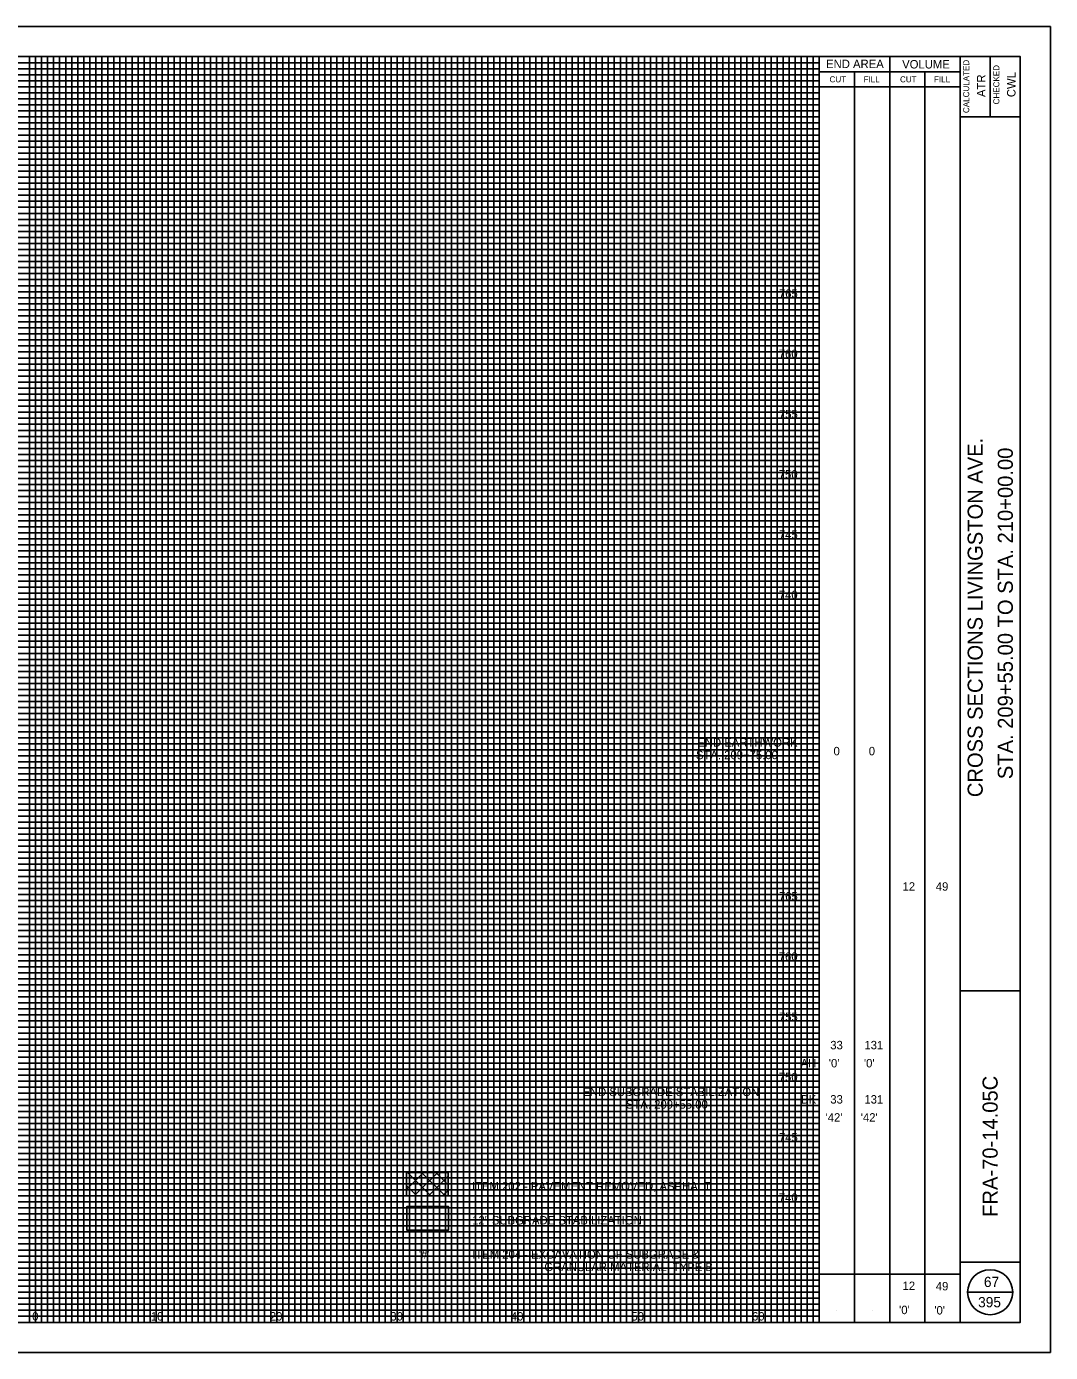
# Model space of a CAD drawing. Extents: x -10 to 160, y -2 to 568.
# Drawn here: x 75.1 to 160, y 457.5 to 567.5 of the extents above; entities that cross this region are included whole.
import ezdxf

# ---------------------------------------------------------------- set-up
doc = ezdxf.new("R2010")
doc.units = 0
for name, color, linetype in [('DR_P_Text', 7, 'Continuous'), ('SH_Border', 7, 'Continuous'), ('SH_Cut_Line', 7, 'Continuous'), ('SH_Data', 7, 'Continuous'), ('SH_Major_Grid_Line', 7, 'Continuous'), ('SH_Minor_Grid_Line', 7, 'Continuous'), ('XS_P_Annotation', 7, 'Continuous'), ('XS_P_Undercut', 7, 'Continuous'), ('XS_X_Pavt', 7, 'Continuous')]:
    doc.layers.add(name, color=color, linetype=linetype)

msp = doc.modelspace()

# ---------------------------------------------------------------- linework, layer by layer
at = {"layer": 'SH_Border'}
for p, q in [((152.5, 460), (152.5, 565)), ((155, 565), (155, 560)), ((152.5, 560), (157.5, 560)), ((152.5, 487.5), (157.5, 487.5)), ((152.5, 465), (157.5, 465))]:
    msp.add_line(p, q, dxfattribs=at)
msp.add_lwpolyline([(0, 565), (157.5, 565), (157.5, 460), (0, 460)], close=True, dxfattribs=at)
at = {"layer": 'SH_Cut_Line'}
msp.add_lwpolyline([(-10, 457.5), (160, 457.5), (160, 567.5), (-10, 567.5)], close=True, dxfattribs=at)
at = {"layer": 'SH_Data'}
for p, q in [((140.83, 460), (140.83, 565)), ((146.67, 460), (146.67, 565)), ((140.83, 563.75), (152.5, 563.75)), ((143.75, 460), (143.75, 563.75)), ((149.58, 460), (149.58, 563.75)), ((140.83, 562.5), (152.5, 562.5)), ((140.83, 464), (152.5, 464)), ((153.12, 462.5), (156.88, 462.5)), ((142.29, 461), (142.29, 461)), ((145.21, 461), (145.21, 461)), ((148.12, 461), (148.12, 461)), ((151.04, 461), (151.04, 461))]:
    msp.add_line(p, q, dxfattribs=at)
msp.add_circle((155, 462.5), 1.87, dxfattribs=at)
at = {"layer": 'SH_Major_Grid_Line'}
for p, q in [((75.83, 460), (75.83, 565)), ((80.83, 460), (80.83, 565)), ((85.83, 460), (85.83, 565)), ((90.83, 460), (90.83, 565)), ((95.83, 460), (95.83, 565)), ((100.83, 460), (100.83, 565)), ((105.83, 460), (105.83, 565)), ((110.83, 460), (110.83, 565)), ((115.83, 460), (115.83, 565)), ((120.83, 460), (120.83, 565)), ((125.83, 460), (125.83, 565)), ((130.83, 460), (130.83, 565)), ((135.83, 460), (135.83, 565)), ((5.83, 560), (140.83, 560)), ((5.83, 555), (140.83, 555)), ((5.83, 550), (140.83, 550)), ((5.83, 545), (140.83, 545)), ((5.83, 540), (140.83, 540)), ((5.83, 535), (140.83, 535)), ((5.83, 530), (140.83, 530)), ((5.83, 525), (140.83, 525)), ((5.83, 520), (140.83, 520)), ((5.83, 515), (140.83, 515)), ((5.83, 510), (140.83, 510)), ((5.83, 505), (140.83, 505)), ((5.83, 500), (140.83, 500)), ((5.83, 495), (140.83, 495)), ((5.83, 490), (140.83, 490)), ((5.83, 485), (140.83, 485)), ((5.83, 480), (140.83, 480)), ((5.83, 475), (140.83, 475)), ((5.83, 470), (140.83, 470)), ((5.83, 465), (140.83, 465))]:
    msp.add_line(p, q, dxfattribs=at)
at = {"layer": 'SH_Minor_Grid_Line'}
for p, q in [((5.83, 564.5), (140.83, 564.5)), ((75.33, 460), (75.33, 565)), ((76.33, 460), (76.33, 565)), ((76.83, 460), (76.83, 565)), ((77.33, 460), (77.33, 565)), ((77.83, 460), (77.83, 565)), ((78.33, 460), (78.33, 565)), ((78.83, 460), (78.83, 565)), ((79.33, 460), (79.33, 565)), ((79.83, 460), (79.83, 565)), ((80.33, 460), (80.33, 565)), ((81.33, 460), (81.33, 565)), ((81.83, 460), (81.83, 565)), ((82.33, 460), (82.33, 565)), ((82.83, 460), (82.83, 565)), ((83.33, 460), (83.33, 565)), ((83.83, 460), (83.83, 565)), ((84.33, 460), (84.33, 565)), ((84.83, 460), (84.83, 565)), ((85.33, 460), (85.33, 565)), ((86.33, 460), (86.33, 565)), ((86.83, 460), (86.83, 565)), ((87.33, 460), (87.33, 565)), ((87.83, 460), (87.83, 565)), ((88.33, 460), (88.33, 565)), ((88.83, 460), (88.83, 565)), ((89.33, 460), (89.33, 565)), ((89.83, 460), (89.83, 565)), ((90.33, 460), (90.33, 565)), ((91.33, 460), (91.33, 565)), ((91.83, 460), (91.83, 565)), ((92.33, 460), (92.33, 565)), ((92.83, 460), (92.83, 565)), ((93.33, 460), (93.33, 565)), ((93.83, 460), (93.83, 565)), ((94.33, 460), (94.33, 565)), ((94.83, 460), (94.83, 565)), ((95.33, 460), (95.33, 565)), ((96.33, 460), (96.33, 565)), ((96.83, 460), (96.83, 565)), ((97.33, 460), (97.33, 565)), ((97.83, 460), (97.83, 565)), ((98.33, 460), (98.33, 565)), ((98.83, 460), (98.83, 565)), ((99.33, 460), (99.33, 565)), ((99.83, 460), (99.83, 565)), ((100.33, 460), (100.33, 565)), ((101.33, 460), (101.33, 565)), ((101.83, 460), (101.83, 565)), ((102.33, 460), (102.33, 565)), ((102.83, 460), (102.83, 565)), ((103.33, 460), (103.33, 565)), ((103.83, 460), (103.83, 565)), ((104.33, 460), (104.33, 565)), ((104.83, 460), (104.83, 565)), ((105.33, 460), (105.33, 565)), ((106.33, 460), (106.33, 565)), ((106.83, 460), (106.83, 565)), ((107.33, 460), (107.33, 565)), ((107.83, 460), (107.83, 565)), ((108.33, 460), (108.33, 565)), ((108.83, 460), (108.83, 565)), ((109.33, 460), (109.33, 565)), ((109.83, 460), (109.83, 565)), ((110.33, 460), (110.33, 565)), ((111.33, 460), (111.33, 565)), ((111.83, 460), (111.83, 565)), ((112.33, 460), (112.33, 565)), ((112.83, 460), (112.83, 565)), ((113.33, 460), (113.33, 565)), ((113.83, 460), (113.83, 565)), ((114.33, 460), (114.33, 565)), ((114.83, 460), (114.83, 565)), ((115.33, 460), (115.33, 565)), ((116.33, 460), (116.33, 565)), ((116.83, 460), (116.83, 565)), ((117.33, 460), (117.33, 565)), ((117.83, 460), (117.83, 565)), ((118.33, 460), (118.33, 565)), ((118.83, 460), (118.83, 565)), ((119.33, 460), (119.33, 565)), ((119.83, 460), (119.83, 565)), ((120.33, 460), (120.33, 565)), ((121.33, 460), (121.33, 565)), ((121.83, 460), (121.83, 565)), ((122.33, 460), (122.33, 565)), ((122.83, 460), (122.83, 565)), ((123.33, 460), (123.33, 565)), ((123.83, 460), (123.83, 565)), ((124.33, 460), (124.33, 565)), ((124.83, 460), (124.83, 565)), ((125.33, 460), (125.33, 565)), ((126.33, 460), (126.33, 565)), ((126.83, 460), (126.83, 565)), ((127.33, 460), (127.33, 565)), ((127.83, 460), (127.83, 565)), ((128.33, 460), (128.33, 565)), ((128.83, 460), (128.83, 565)), ((129.33, 460), (129.33, 565)), ((129.83, 460), (129.83, 565)), ((130.33, 460), (130.33, 565)), ((131.33, 460), (131.33, 565)), ((131.83, 460), (131.83, 565)), ((132.33, 460), (132.33, 565)), ((132.83, 460), (132.83, 565)), ((133.33, 460), (133.33, 565)), ((133.83, 460), (133.83, 565)), ((134.33, 460), (134.33, 565)), ((134.83, 460), (134.83, 565)), ((135.33, 460), (135.33, 565)), ((136.33, 460), (136.33, 565)), ((136.83, 460), (136.83, 565)), ((137.33, 460), (137.33, 565)), ((137.83, 460), (137.83, 565)), ((138.33, 460), (138.33, 565)), ((138.83, 460), (138.83, 565)), ((139.33, 460), (139.33, 565)), ((139.83, 460), (139.83, 565)), ((140.33, 460), (140.33, 565)), ((5.83, 564), (140.83, 564)), ((5.83, 563.5), (140.83, 563.5)), ((5.83, 563), (140.83, 563)), ((5.83, 562.5), (140.83, 562.5)), ((5.83, 562), (140.83, 562)), ((5.83, 561.5), (140.83, 561.5)), ((5.83, 561), (140.83, 561)), ((5.83, 560.5), (140.83, 560.5)), ((5.83, 559.5), (140.83, 559.5)), ((5.83, 559), (140.83, 559)), ((5.83, 558.5), (140.83, 558.5)), ((5.83, 558), (140.83, 558)), ((5.83, 557.5), (140.83, 557.5)), ((5.83, 557), (140.83, 557)), ((5.83, 556.5), (140.83, 556.5)), ((5.83, 556), (140.83, 556)), ((5.83, 555.5), (140.83, 555.5)), ((5.83, 554.5), (140.83, 554.5)), ((5.83, 554), (140.83, 554)), ((5.83, 553.5), (140.83, 553.5)), ((5.83, 553), (140.83, 553)), ((5.83, 552.5), (140.83, 552.5)), ((5.83, 552), (140.83, 552)), ((5.83, 551.5), (140.83, 551.5)), ((5.83, 551), (140.83, 551)), ((5.83, 550.5), (140.83, 550.5)), ((5.83, 549.5), (140.83, 549.5)), ((5.83, 549), (140.83, 549)), ((5.83, 548.5), (140.83, 548.5)), ((5.83, 548), (140.83, 548)), ((5.83, 547.5), (140.83, 547.5)), ((5.83, 547), (140.83, 547)), ((5.83, 546.5), (140.83, 546.5)), ((5.83, 546), (140.83, 546)), ((5.83, 545.5), (140.83, 545.5)), ((5.83, 544.5), (140.83, 544.5)), ((5.83, 544), (140.83, 544)), ((5.83, 543.5), (140.83, 543.5)), ((5.83, 543), (140.83, 543)), ((5.83, 542.5), (140.83, 542.5)), ((5.83, 542), (140.83, 542)), ((5.83, 541.5), (140.83, 541.5)), ((5.83, 541), (140.83, 541)), ((5.83, 540.5), (140.83, 540.5)), ((5.83, 539.5), (140.83, 539.5)), ((5.83, 539), (140.83, 539)), ((5.83, 538.5), (140.83, 538.5)), ((5.83, 538), (140.83, 538)), ((5.83, 537.5), (140.83, 537.5)), ((5.83, 537), (140.83, 537)), ((5.83, 536.5), (140.83, 536.5)), ((5.83, 536), (140.83, 536)), ((5.83, 535.5), (140.83, 535.5)), ((5.83, 534.5), (140.83, 534.5)), ((5.83, 534), (140.83, 534)), ((5.83, 533.5), (140.83, 533.5)), ((5.83, 533), (140.83, 533)), ((5.83, 532.5), (140.83, 532.5)), ((5.83, 532), (140.83, 532)), ((5.83, 531.5), (140.83, 531.5)), ((5.83, 531), (140.83, 531)), ((5.83, 530.5), (140.83, 530.5)), ((5.83, 529.5), (140.83, 529.5)), ((5.83, 529), (140.83, 529)), ((5.83, 528.5), (140.83, 528.5)), ((5.83, 528), (140.83, 528)), ((5.83, 527.5), (140.83, 527.5)), ((5.83, 527), (140.83, 527)), ((5.83, 526.5), (140.83, 526.5)), ((5.83, 526), (140.83, 526)), ((5.83, 525.5), (140.83, 525.5)), ((5.83, 524.5), (140.83, 524.5)), ((5.83, 524), (140.83, 524)), ((5.83, 523.5), (140.83, 523.5)), ((5.83, 523), (140.83, 523)), ((5.83, 522.5), (140.83, 522.5)), ((5.83, 522), (140.83, 522)), ((5.83, 521.5), (140.83, 521.5)), ((5.83, 521), (140.83, 521)), ((5.83, 520.5), (140.83, 520.5)), ((5.83, 519.5), (140.83, 519.5)), ((5.83, 519), (140.83, 519)), ((5.83, 518.5), (140.83, 518.5)), ((5.83, 518), (140.83, 518)), ((5.83, 517.5), (140.83, 517.5)), ((5.83, 517), (140.83, 517)), ((5.83, 516.5), (140.83, 516.5)), ((5.83, 516), (140.83, 516)), ((5.83, 515.5), (140.83, 515.5)), ((5.83, 514.5), (140.83, 514.5)), ((5.83, 514), (140.83, 514)), ((5.83, 513.5), (140.83, 513.5)), ((5.83, 513), (140.83, 513)), ((5.83, 512.5), (140.83, 512.5)), ((5.83, 512), (140.83, 512)), ((5.83, 511.5), (140.83, 511.5)), ((5.83, 511), (140.83, 511)), ((5.83, 510.5), (140.83, 510.5)), ((5.83, 509.5), (140.83, 509.5)), ((5.83, 509), (140.83, 509)), ((5.83, 508.5), (140.83, 508.5)), ((5.83, 508), (140.83, 508)), ((5.83, 507.5), (140.83, 507.5)), ((5.83, 507), (140.83, 507)), ((5.83, 506.5), (140.83, 506.5)), ((5.83, 506), (140.83, 506)), ((5.83, 505.5), (140.83, 505.5)), ((5.83, 504.5), (140.83, 504.5)), ((5.83, 504), (140.83, 504)), ((5.83, 503.5), (140.83, 503.5)), ((5.83, 503), (140.83, 503)), ((5.83, 502.5), (140.83, 502.5)), ((5.83, 502), (140.83, 502)), ((5.83, 501.5), (140.83, 501.5)), ((5.83, 501), (140.83, 501)), ((5.83, 500.5), (140.83, 500.5)), ((5.83, 499.5), (140.83, 499.5)), ((5.83, 499), (140.83, 499)), ((5.83, 498.5), (140.83, 498.5)), ((5.83, 498), (140.83, 498)), ((5.83, 497.5), (140.83, 497.5)), ((5.83, 497), (140.83, 497)), ((5.83, 496.5), (140.83, 496.5)), ((5.83, 496), (140.83, 496)), ((5.83, 495.5), (140.83, 495.5)), ((5.83, 494.5), (140.83, 494.5)), ((5.83, 494), (140.83, 494)), ((5.83, 493.5), (140.83, 493.5)), ((5.83, 493), (140.83, 493)), ((5.83, 492.5), (140.83, 492.5)), ((5.83, 492), (140.83, 492)), ((5.83, 491.5), (140.83, 491.5)), ((5.83, 491), (140.83, 491)), ((5.83, 490.5), (140.83, 490.5)), ((5.83, 489.5), (140.83, 489.5)), ((5.83, 489), (140.83, 489)), ((5.83, 488.5), (140.83, 488.5)), ((5.83, 488), (140.83, 488)), ((5.83, 487.5), (140.83, 487.5)), ((5.83, 487), (140.83, 487)), ((5.83, 486.5), (140.83, 486.5)), ((5.83, 486), (140.83, 486)), ((5.83, 485.5), (140.83, 485.5)), ((5.83, 484.5), (140.83, 484.5)), ((5.83, 484), (140.83, 484)), ((5.83, 483.5), (140.83, 483.5)), ((5.83, 483), (140.83, 483)), ((5.83, 482.5), (140.83, 482.5)), ((5.83, 482), (140.83, 482)), ((5.83, 481.5), (140.83, 481.5)), ((5.83, 481), (140.83, 481)), ((5.83, 480.5), (140.83, 480.5)), ((5.83, 479.5), (140.83, 479.5)), ((5.83, 479), (140.83, 479)), ((5.83, 478.5), (140.83, 478.5)), ((5.83, 478), (140.83, 478)), ((5.83, 477.5), (140.83, 477.5)), ((5.83, 477), (140.83, 477)), ((5.83, 476.5), (140.83, 476.5)), ((5.83, 476), (140.83, 476)), ((5.83, 475.5), (140.83, 475.5)), ((5.83, 474.5), (140.83, 474.5)), ((5.83, 474), (140.83, 474)), ((5.83, 473.5), (140.83, 473.5)), ((5.83, 473), (140.83, 473)), ((5.83, 472.5), (140.83, 472.5)), ((5.83, 472), (140.83, 472)), ((5.83, 471.5), (140.83, 471.5)), ((5.83, 471), (140.83, 471)), ((5.83, 470.5), (140.83, 470.5)), ((5.83, 469.5), (140.83, 469.5)), ((5.83, 469), (140.83, 469)), ((5.83, 468.5), (140.83, 468.5)), ((5.83, 468), (140.83, 468)), ((5.83, 467.5), (140.83, 467.5)), ((5.83, 467), (140.83, 467)), ((5.83, 466.5), (140.83, 466.5)), ((5.83, 466), (140.83, 466)), ((5.83, 465.5), (140.83, 465.5)), ((5.83, 464.5), (140.83, 464.5)), ((5.83, 464), (140.83, 464)), ((5.83, 463.5), (140.83, 463.5)), ((5.83, 463), (140.83, 463)), ((5.83, 462.5), (140.83, 462.5)), ((5.83, 462), (140.83, 462)), ((5.83, 461.5), (140.83, 461.5)), ((5.83, 461), (140.83, 461)), ((5.83, 460.5), (140.83, 460.5))]:
    msp.add_line(p, q, dxfattribs=at)
at = {"layer": 'XS_P_Annotation'}
for points in [[(106.59, 472.43), (110.05, 472.43), (110.05, 470.49), (106.59, 470.49)], [(106.61, 469.6), (110.08, 469.6), (110.08, 467.66), (106.61, 467.66)]]:
    msp.add_lwpolyline(points, close=True, dxfattribs=at)
at = {"layer": 'XS_P_Undercut'}
msp.add_lwpolyline([(106.61, 467.66), (110.08, 467.66), (110.08, 469.6), (106.61, 469.6), (106.61, 467.66)], dxfattribs=at)
at = {"layer": 'XS_X_Pavt'}
for p, q in [((106.59, 471.01), (108, 472.43)), ((106.68, 472.43), (108.62, 470.49)), ((107.24, 470.49), (109.18, 472.43)), ((107.85, 472.43), (109.8, 470.49)), ((108.42, 470.49), (110.05, 472.12)), ((109.03, 472.43), (110.05, 471.41)), ((106.59, 471.34), (107.44, 470.49)), ((109.59, 470.49), (110.05, 470.95))]:
    msp.add_line(p, q, dxfattribs=at)

# ---------------------------------------------------------------- texts
at = {"layer": 'DR_P_Text'}
for s, p in [('765', (137.48, 545)), ('760', (137.47, 540)), ('755', (137.48, 535)), ('750', (137.47, 530)), ('745', (137.48, 525)), ('740', (137.47, 520)), ('0', (142.01, 507.04)), ('0', (144.93, 507.04)), ('12', (147.73, 495.81)), ('49', (150.49, 495.81)), ('765', (137.48, 495)), ('760', (137.47, 490)), ('755', (137.48, 485)), ('33', (141.74, 482.65)), ('131', (144.57, 482.65)), ('AH', (139.28, 481.15)), ("'0'", (141.62, 481.15)), ("'0'", (144.53, 481.15)), ('750', (137.47, 480)), ('BK', (139.32, 478.15)), ('33', (141.74, 478.15)), ('131', (144.57, 478.15)), ("'42'", (141.35, 476.65)), ("'42'", (144.27, 476.65)), ('745', (137.48, 475)), ('740', (137.47, 470)), ("'#'", (107.62, 465.29)), ('12', (147.73, 462.68)), ('49', (150.49, 462.65)), ("'0'", (147.45, 460.68)), ("'0'", (150.37, 460.65)), ('0', (75.55, 460.15)), ('0', (75.55, 460.15)), ('10', (85.39, 460.15)), ('20', (95.26, 460.15)), ('30', (105.25, 460.15)), ('40', (115.25, 460.15)), ('50', (125.25, 460.15)), ('60', (135.25, 460.15))]:
    msp.add_text(s, height=0.7, dxfattribs=at).set_placement(p)
at = {"layer": 'SH_Data'}
for s, height, p in [('END AREA', 0.7, (141.39, 564.05)), ('VOLUME', 0.7, (147.7, 564.02)), ('CUT', 0.5, (141.68, 562.87)), ('FILL', 0.5, (144.5, 562.87)), ('CUT', 0.5, (147.52, 562.87)), ('FILL', 0.5, (150.34, 562.87)), ('67', 0.85, (154.48, 462.93)), ('395', 0.85, (154, 461.25))]:
    msp.add_text(s, height=height, dxfattribs=at).set_placement(p)
for s, height, p in [('CALCULATED', 0.5, (153.26, 560.32)), ('ATR', 0.7, (154.6, 561.65)), ('CHECKED', 0.5, (155.76, 561.04)), ('CWL', 0.7, (157.1, 561.64)), ('CROSS SECTIONS LIVINGSTON AVE.', 1.25, (154.38, 503.57)), ('STA. 209+55.00 TO STA. 210+00.00', 1.25, (156.88, 505.06)), ('FRA-70-14.05C', 1.25, (155.62, 468.75))]:
    msp.add_text(s, height=height, rotation=90, dxfattribs=at).set_placement(p)
at = {"layer": 'XS_P_Annotation'}
for s, p in [('END EARTHWORK', (130.71, 507.76)), ('STA. 209+75.00', (130.6, 506.72)), ('END SUBGRADE STABILIZATION', (121.18, 478.77)), ('STA. 209+55.00', (124.79, 477.73)), ('ITEM 202 - PAVEMENT REMOVED, ASPHALT', (112.02, 470.95)), ('12" SUBGRADE STABILIZATION', (112.04, 468.12)), ('ITEM 204 - EXCAVATION OF SUBGRADE &', (112.04, 465.29)), ('GRANULAR MATERIAL, TYPE B', (118.02, 464.25))]:
    msp.add_text(s, height=0.7, dxfattribs=at).set_placement(p)

doc.saveas('drawing.dxf')
